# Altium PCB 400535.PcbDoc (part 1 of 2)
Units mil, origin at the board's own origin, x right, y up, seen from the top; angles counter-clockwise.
Board outline 2125.98 x 2500 mil, 4 copper layers (Top Layer, Mid-Layer 1, Mid-Layer 2, Bottom Layer), stack 93.792 mil thick; 80 components, 40 nets, 250 pads, 682 vias.
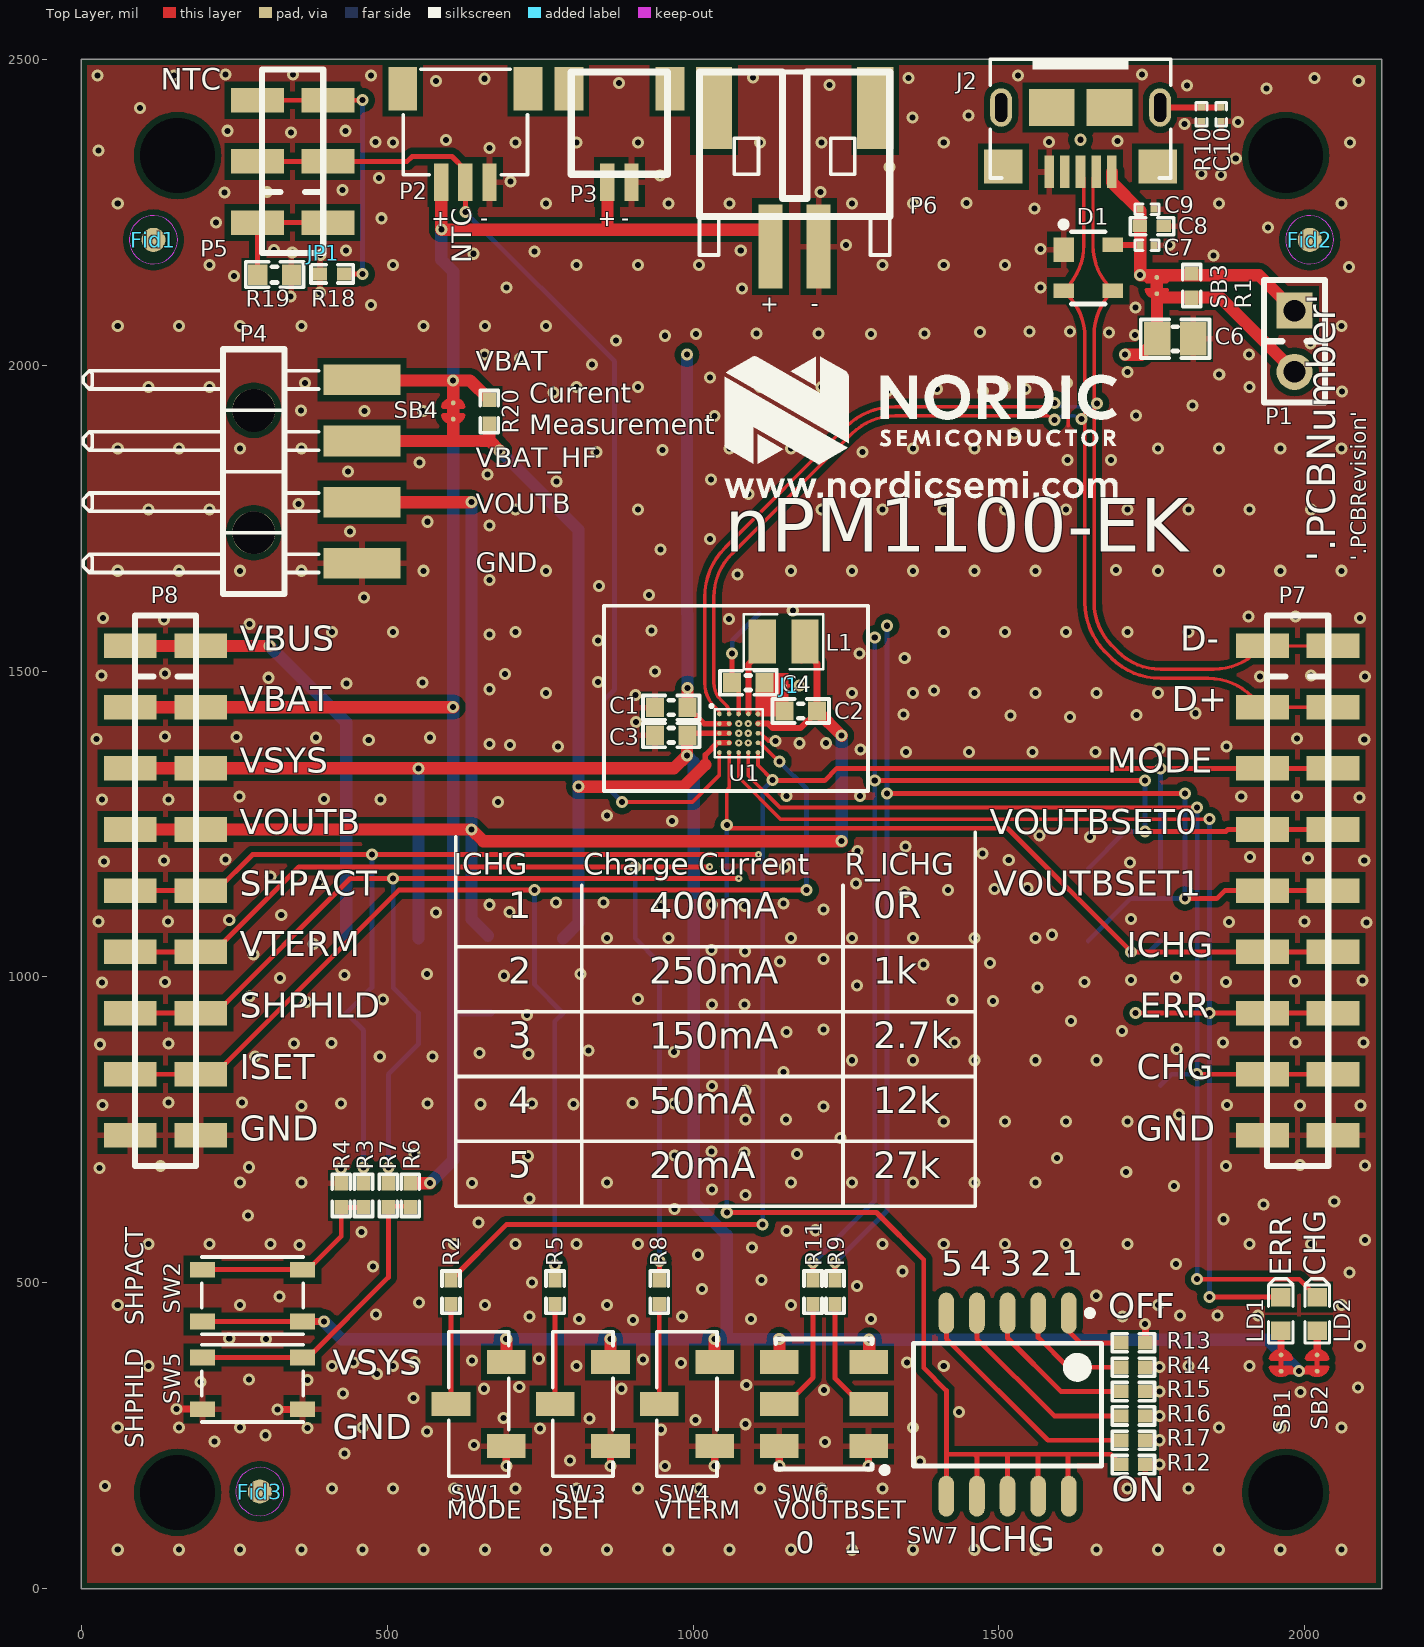
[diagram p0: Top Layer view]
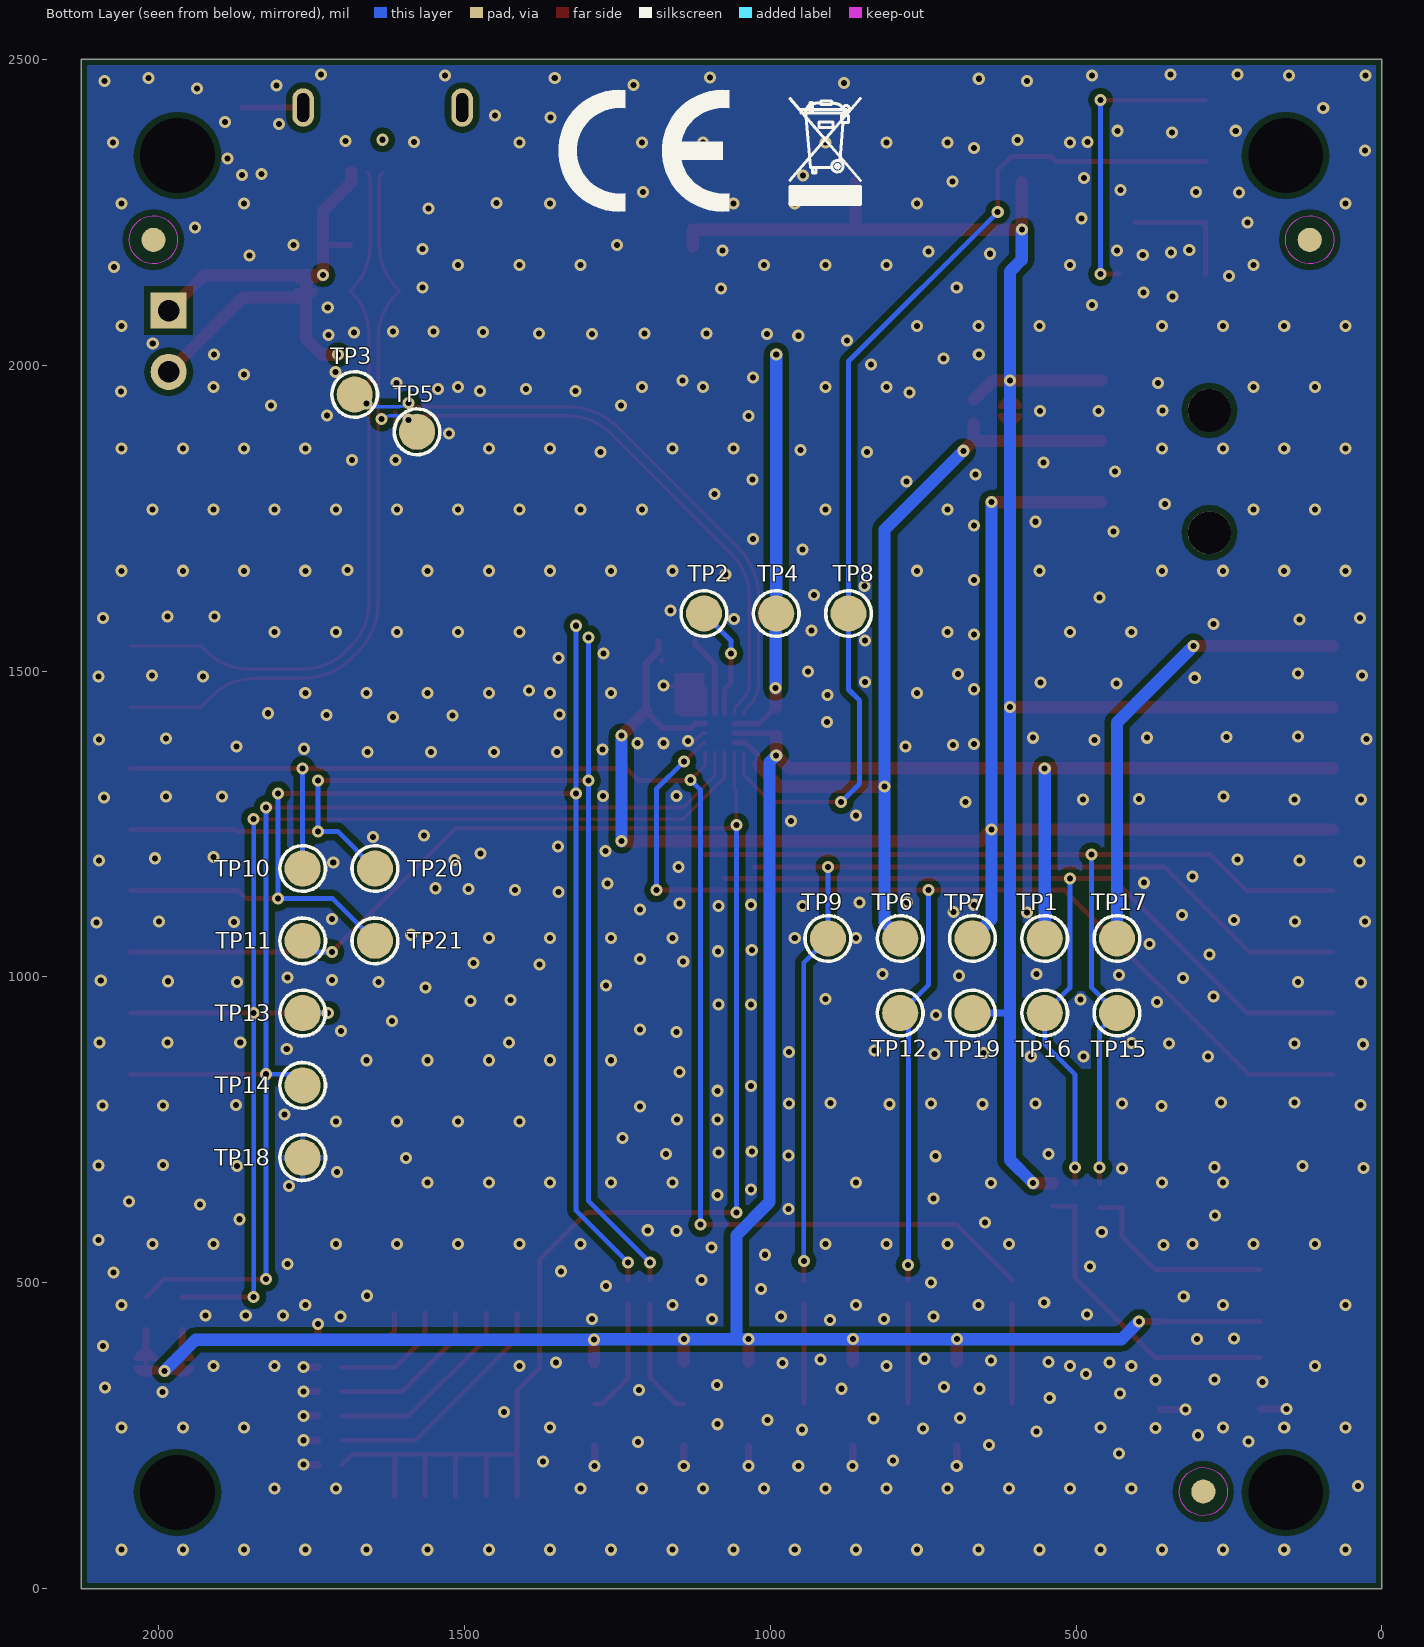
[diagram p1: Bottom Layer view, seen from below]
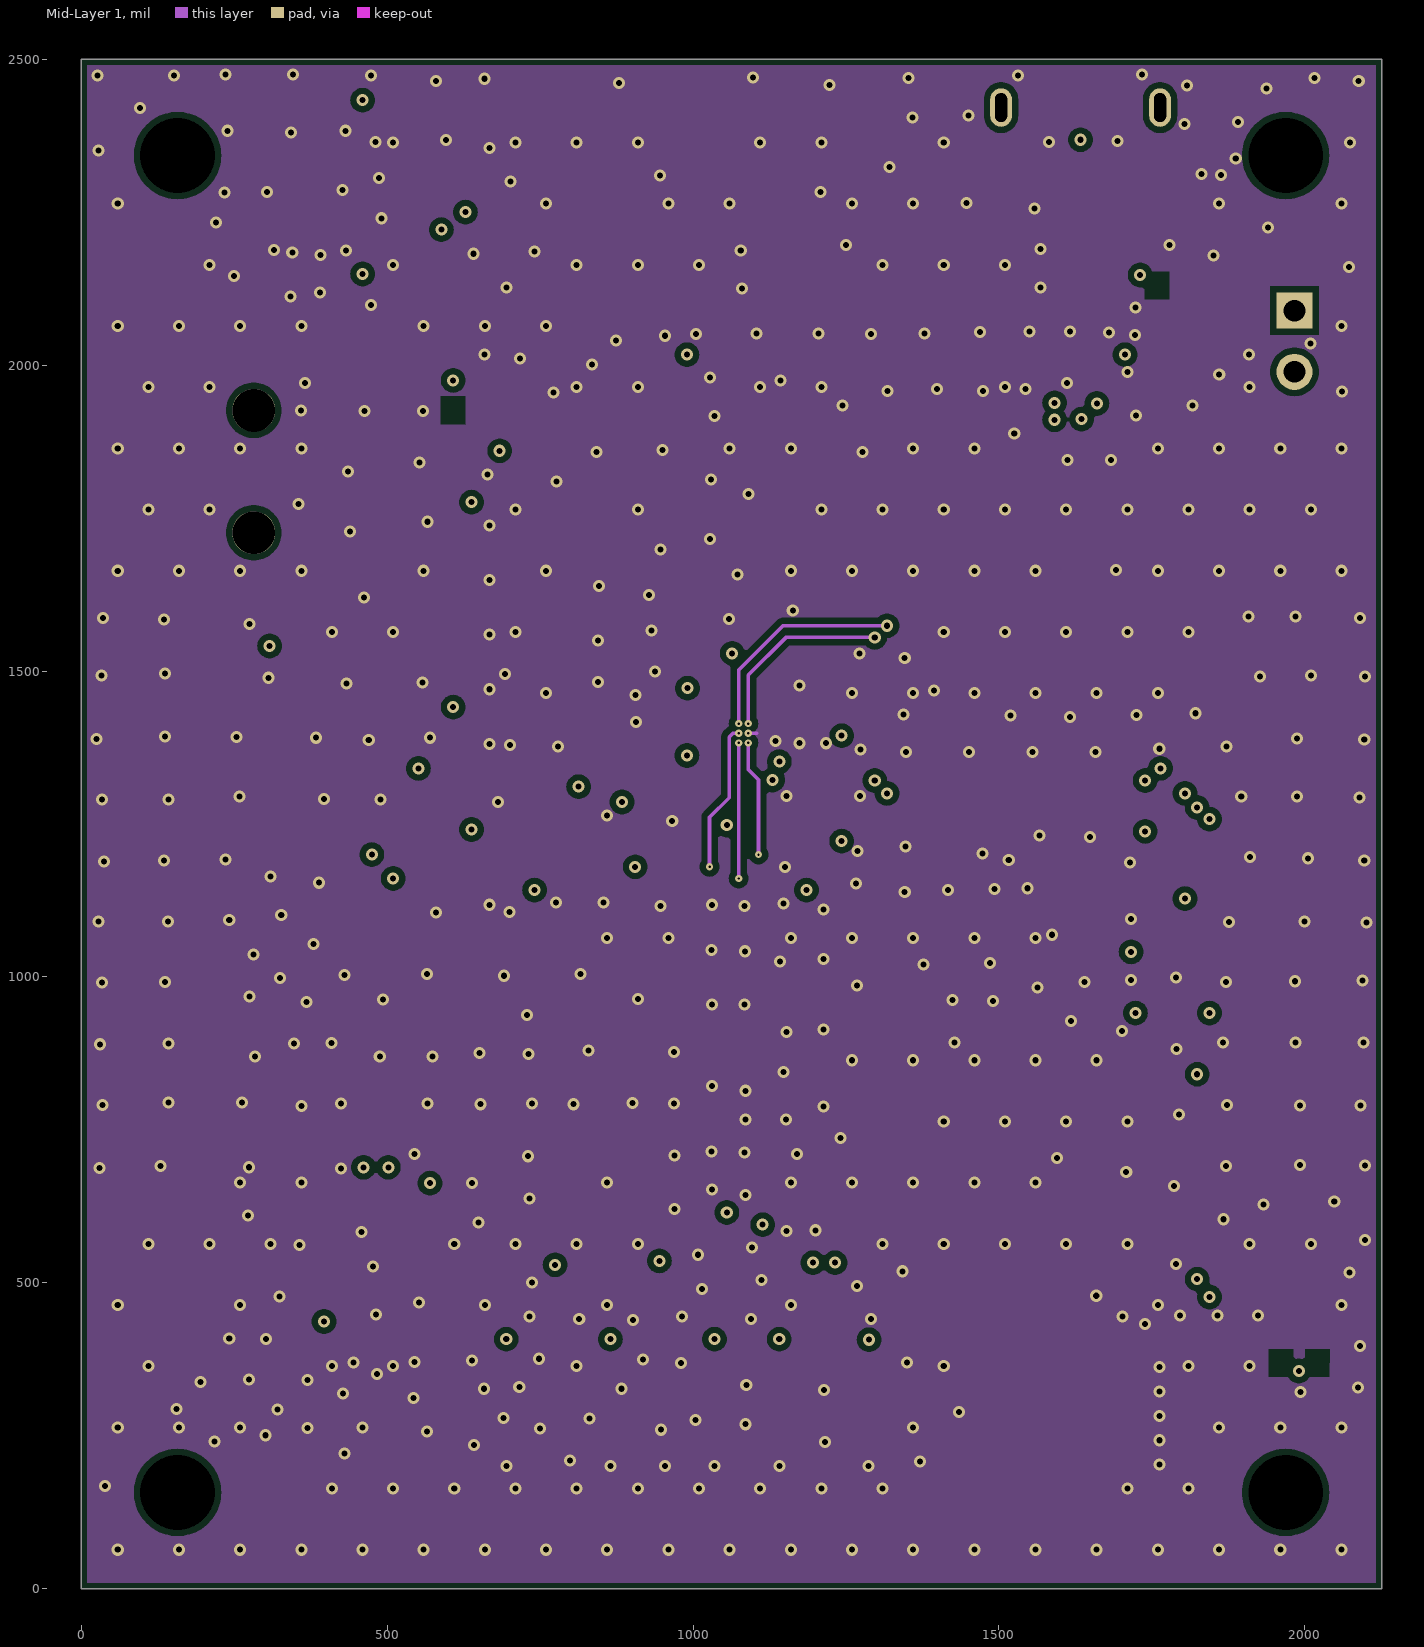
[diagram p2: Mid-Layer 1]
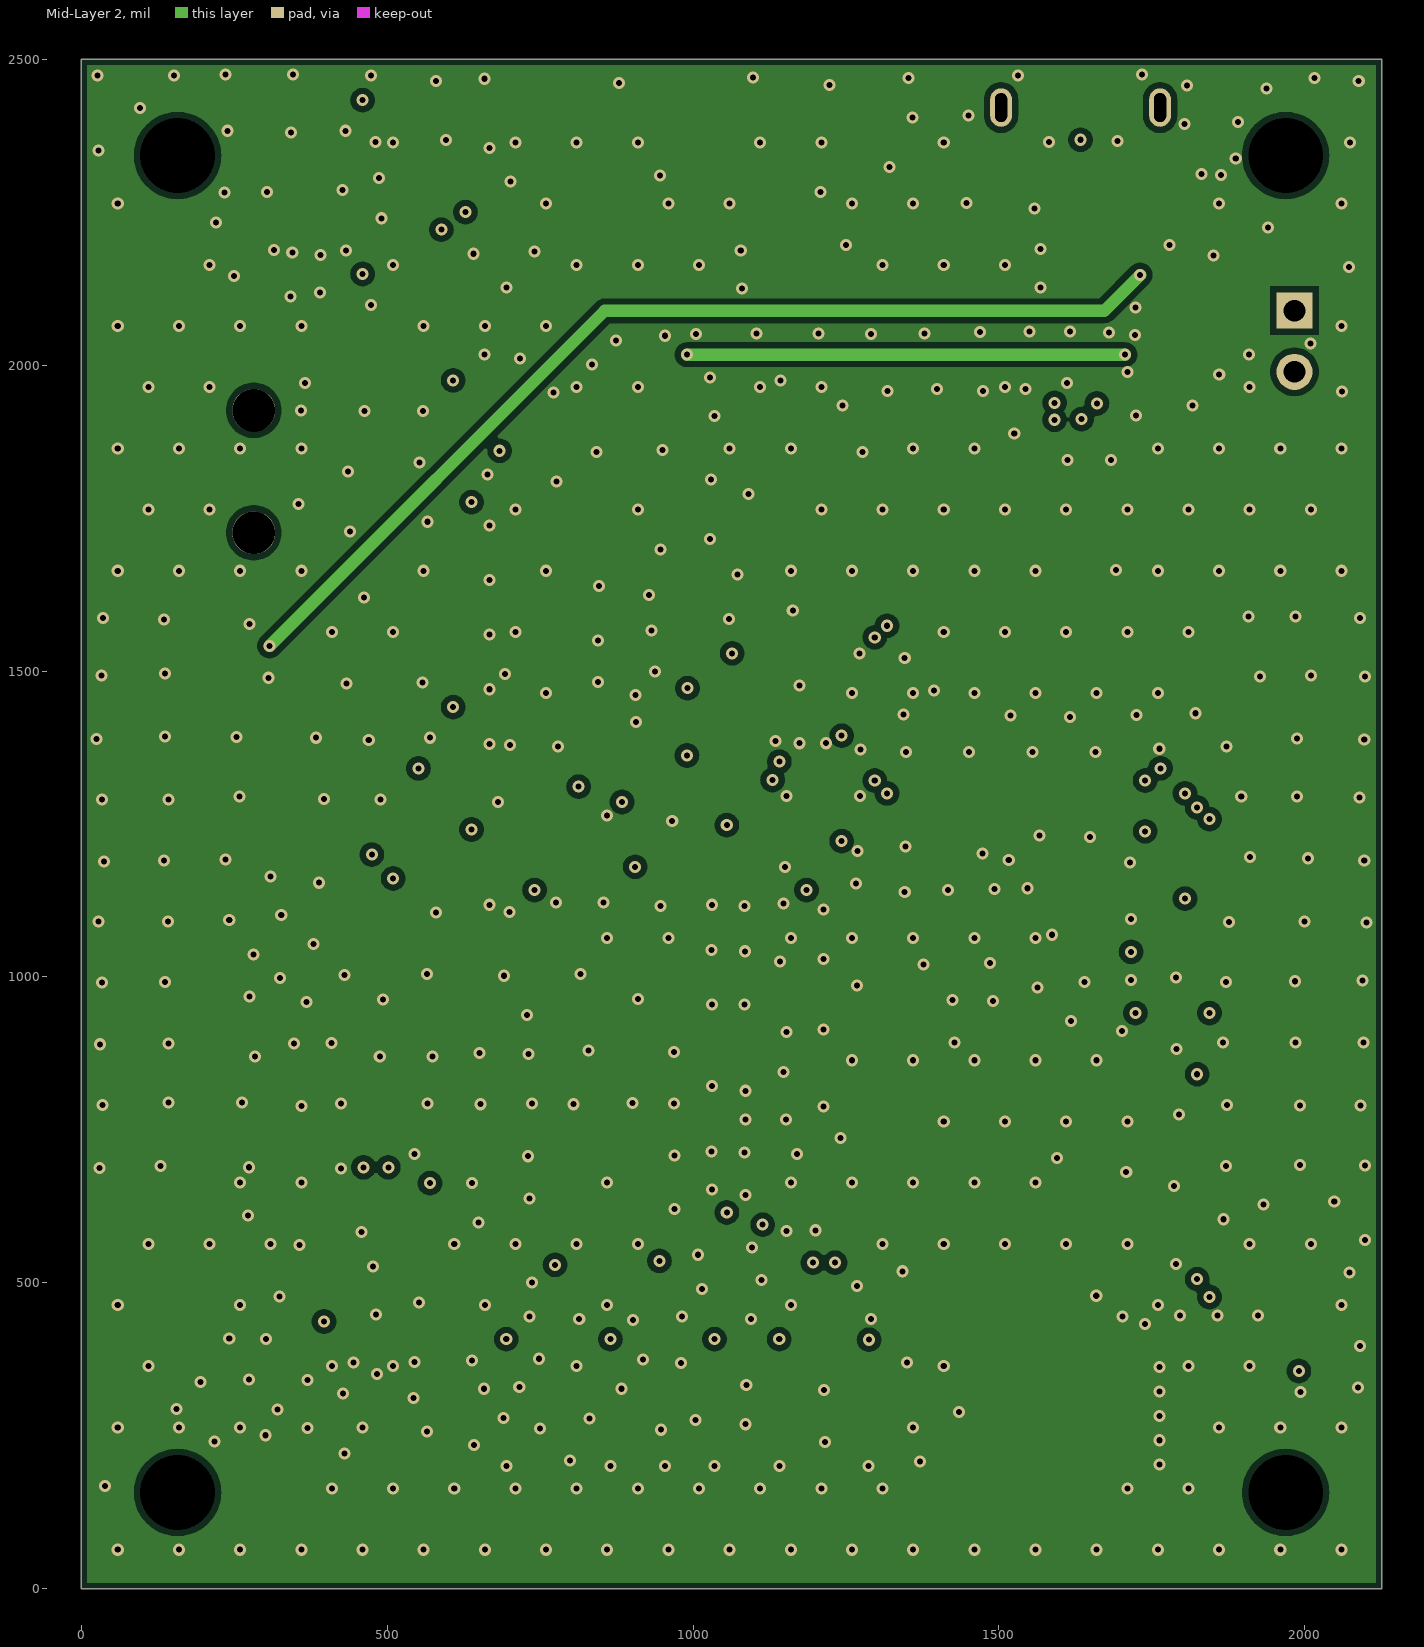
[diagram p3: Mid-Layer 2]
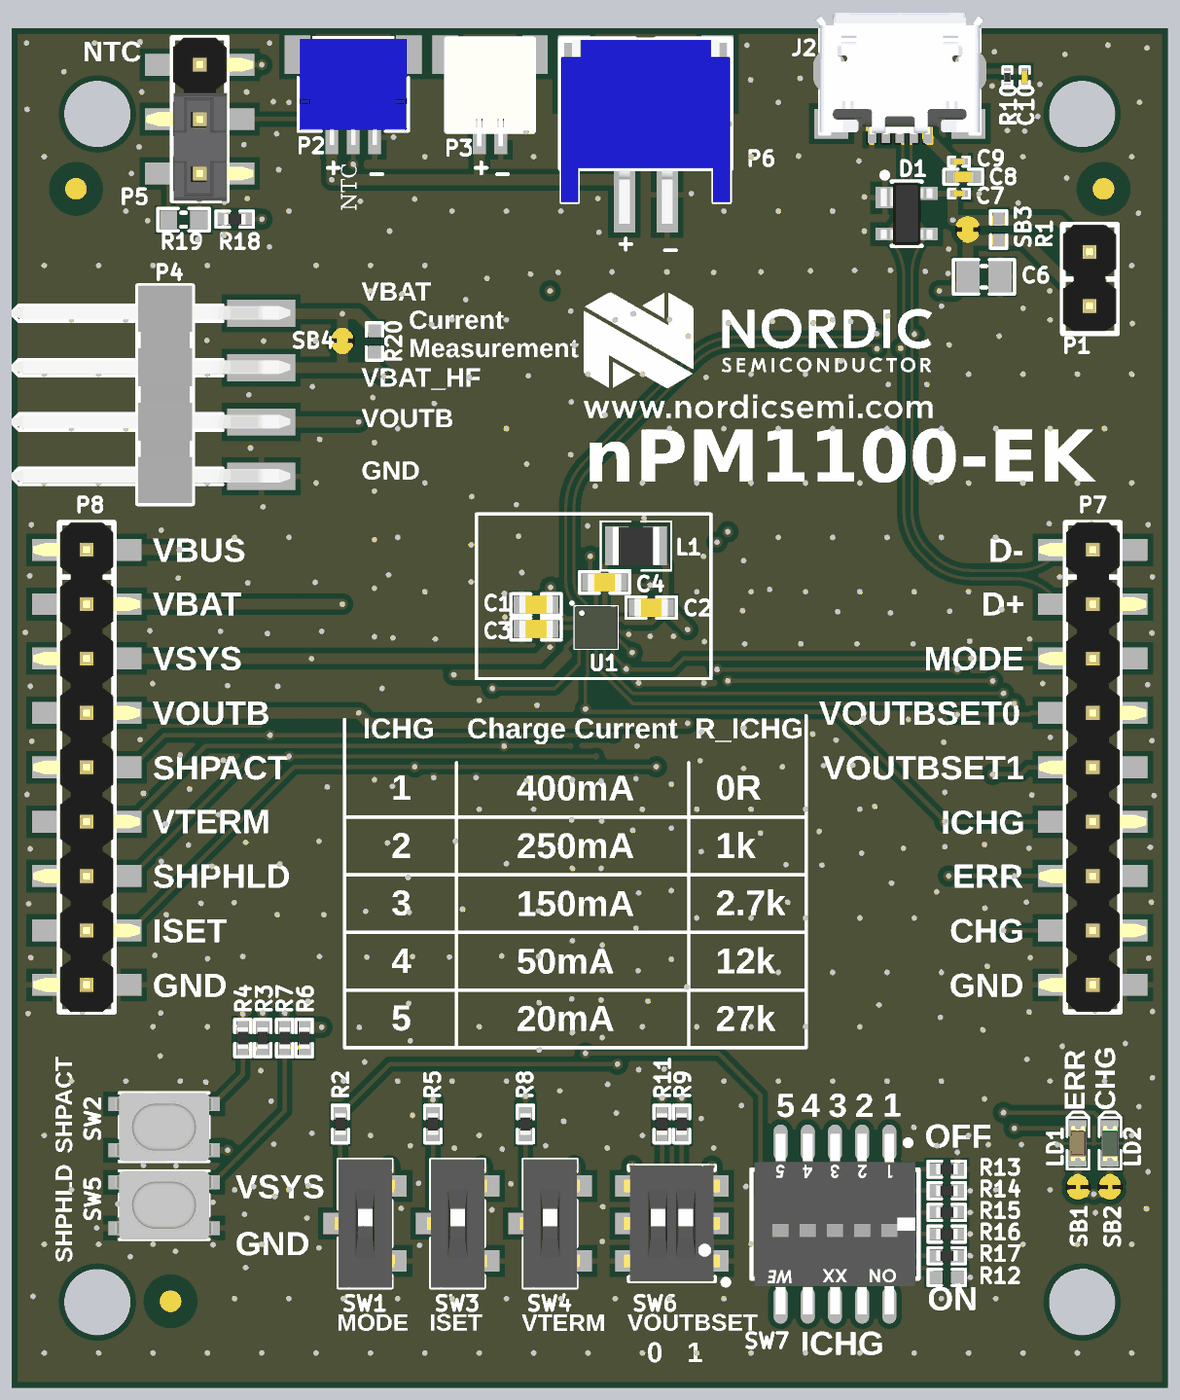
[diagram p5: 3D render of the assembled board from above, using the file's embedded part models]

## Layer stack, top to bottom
Top Solder: solder mask 0.4, Solder Resist, Dk 3.5
Top Layer: signal copper 1.4
Dielectric1: prepreg 62.9921, FR-4, Dk 4.8
Mid-Layer 1: signal copper 1.4
Dielectric2: core 12.6, FR-4, Dk 4.8
Mid-Layer 2: signal copper 1.4
Dielectric3: prepreg 12.6, FR-4, Dk 4.8
Bottom Layer: signal copper 1.4
Bottom Solder: solder mask 0.4, Solder Resist, Dk 3.5

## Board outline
0,0 2125.98,0 2125.98,2500 0,2500

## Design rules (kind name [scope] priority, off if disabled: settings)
BoardOutlineClearance [All] p1: gap=10 ignorepadtopadclearanceinfootprint=FALSE except(0: Arc-SplitContinuation Track-SplitContinuation SMDPad-SplitContinuation THPad-SplitContinuation Via-SplitContinuation Fill-SplitContinuation Poly-SplitContinuation Region-SplitContinuation Text-SplitContinuation)
Clearance Clearance_microvia [AsMM(ViaDiameter) = 0.3 vs AsMM(ViaDiameter) = 0.3] p1: gap=3.94 ignorepadtopadclearanceinfootprint=FALSE except(0: Arc-Hole Track-Hole SMDPad-Hole THPad-Hole Via-Hole Fill-Hole Poly-Hole Region-Hole Text-Hole)
Clearance ANT_Clerance [InNet('ANT')] p2: gap=5 ignorepadtopadclearanceinfootprint=FALSE except(0: Arc-Hole Track-Hole SMDPad-Hole THPad-Hole Via-Hole Fill-Hole Poly-Hole Region-Hole Text-Hole)
Clearance Polygon_Clearance [(InNamedPolygon('Top_Layer-GND')) or (InNamedPolygon('Bottom_Layer-GND')) or (InNamedPolygon('Mid_Layer_1-GND')) or (InNamedPolygon('Mid_Layer_2-GND'))] p3: gap=10 ignorepadtopadclearanceinfootprint=FALSE except(0: Arc-Hole Track-Hole SMDPad-Hole THPad-Hole Via-Hole Fill-Hole Poly-Hole Region-Hole Text-Hole)
Clearance [All] p4: gap=4.92 ignorepadtopadclearanceinfootprint=FALSE
ComponentClearance [All] p1 off: gap=10 collisioncheckmode=3 verticalgap=10 showdistances=FALSE
DiffPairsRouting [All] p1: maxlimit=10 minlimit=9.49 mostfreqgap=10 toplayer_prefgap=9.49 toplayer_minwidth=5.51 toplayer_maxwidth=15 toplayer_prefwidth=5.51 midlayer1_minwidth=5.51 midlayer1_maxwidth=15 midlayer1_prefwidth=11.06 midlayer2_mingap=10 midlayer2_minwidth=15 midlayer2_maxwidth=15 midlayer2_prefwidth=15 bottomlayer_prefgap=9.49 bottomlayer_minwidth=5.51 bottomlayer_maxwidth=15 bottomlayer_prefwidth=5.51 maxuncoupledlength=500
FabricationTestPointUsage TestPointUsage [All] p1: valid=0 allowmultiple=FALSE
FabricationTestpoint Testpoint [All] p1: side=3 testpointundercomponent=TRUE minsize=40 maxsize=100 preferedsize=60 minholesize=0 maxholesize=40 preferedholesize=32 testpointgrid=1 allowsidetop=TRUE allowsidebottom=TRUE usegrid=TRUE gridtolerance=0.01
Height [All] p1 off: minheight=0 maxheight=1000 prefheight=500
HoleSize [All] p1: absolutevalues=TRUE maxlimit=196.85 minlimit=3.94 maxpercent=80.000 minpercent=20.000
HoleToHoleClearance HoleToHoleClearance_L1L2 [InDrillLayerPair('Top Layer - Mid-Layer 1') vs InDrillLayerPair('Top Layer - Mid-Layer 1')] p1: gap=8.86 allowstackedmicrovias=TRUE
HoleToHoleClearance HoleToHoleClearance_L1L2_L1L3 [InDrillLayerPair('Top Layer - Mid-Layer 1') vs InDrillLayerPair('Top Layer - Mid-Layer 2')] p2: gap=8.86 allowstackedmicrovias=TRUE
HoleToHoleClearance HoleToHoleClearance_L1L3 [InDrillLayerPair('Top Layer - Mid-Layer 2') vs InDrillLayerPair('Top Layer - Mid-Layer 2')] p3: gap=8.86 allowstackedmicrovias=TRUE
HoleToHoleClearance HoleToHoleClearance_L1L3_L3L4 [InDrillLayerPair('Top Layer - Mid-Layer 2') vs InDrillLayerPair('Mid-Layer 2 - Mid-Layer 3')] p4: gap=8.86 allowstackedmicrovias=TRUE
HoleToHoleClearance HoleToHoleClearance_L3L4 [InDrillLayerPair('Mid-Layer 2 - Mid-Layer 3') vs InDrillLayerPair('Mid-Layer 2 - Mid-Layer 3')] p5: gap=8.86 allowstackedmicrovias=TRUE
HoleToHoleClearance HoleToHoleClearance_L3L4_L4L6 [InDrillLayerPair('Mid-Layer 2 - Mid-Layer 3') vs InDrillLayerPair('Mid-Layer 3 - Bottom Layer')] p6: gap=8.86 allowstackedmicrovias=TRUE
HoleToHoleClearance HoleToHoleClearance_L4L6 [InDrillLayerPair('Mid-Layer 3 - Bottom Layer') vs InDrillLayerPair('Mid-Layer 3 - Bottom Layer')] p7: gap=8.86 allowstackedmicrovias=TRUE
HoleToHoleClearance HoleToHoleClearance_L1L2_L1L6 [InDrillLayerPair('Top Layer - Mid-Layer 1') vs InDrillLayerPair('Top Layer - Bottom Layer')] p8: gap=10.83 allowstackedmicrovias=FALSE
HoleToHoleClearance HoleToHoleClearance_L1L3_L1L6 [InDrillLayerPair('Top Layer - Mid-Layer 2') vs InDrillLayerPair('Top Layer - Bottom Layer')] p9: gap=10.83 allowstackedmicrovias=FALSE
HoleToHoleClearance HoleToHoleClearance_L3L4_L1L6 [InDrillLayerPair('Mid-Layer 2 - Mid-Layer 3') vs InDrillLayerPair('Top Layer - Bottom Layer')] p10: gap=10.83 allowstackedmicrovias=FALSE
HoleToHoleClearance HoleToHoleClearance_L4L6_L1L6 [InDrillLayerPair('Mid-Layer 3 - Bottom Layer') vs InDrillLayerPair('Top Layer - Bottom Layer')] p11: gap=10.83 allowstackedmicrovias=FALSE
HoleToHoleClearance HoleToHoleClearance_L1L6 [InDrillLayerPair('Top Layer - Bottom Layer') vs InDrillLayerPair('Top Layer - Bottom Layer')] p12: gap=17.72 allowstackedmicrovias=FALSE
MinimumAnnularRing [All] p1 off: minimumring=6
PolygonConnect PolygonConnect_1 [isVia and innet(gnd)] p1: connectstyle=Direct reliefconductorwidth=10 reliefentries=4 polygonreliefangle="90 Angle" airgapwidth=10
PolygonConnect [All] p2: connectstyle=Relief reliefconductorwidth=10 reliefentries=4 polygonreliefangle="90 Angle" airgapwidth=10
RoutingVias [All] p1: holewidth=12 width=24 viastyle="Through Hole" minholewidth=3.94 minwidth=11.81 maxholewidth=28 maxwidth=50 useviatemplates=TRUE viatemplateguid#1={93AF73D0-991B-4F91-A86F-AF45B5E71B0E} viatemplateguid#2={23E904B5-25B2-4AFA-AFBF-BB17C8E28516} viatemplatename#1=v30h10m0 viatemplatename#2=v50h25m0mx0
SilkToSolderMaskClearance SilkscreenOverComponentPads [IsPad] p1: minsilkscreentomaskgap=10 clearancetoexposedcopper=TRUE
SolderMaskExpansion [IsVia] p1: expansion=3 istentingtop=TRUE
Width [All] p1: maxlimit=20 minlimit=5.91 preferedwidth=12 minimp=50.000000 maximp=50.000000 favimp=50.000000
22 further rules are at their usual default settings.

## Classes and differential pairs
component class pca10123_sheet1_cover: Fid1 Fid2 Fid3
component class pca10123-sheet2_nPM1100: C1 C2 C3 C4 J1 L1 TP1 TP2 TP3 TP4 TP5 TP6 TP7 TP8 TP9 TP10 TP11 TP12 TP13 TP14 TP15 TP16 TP18 TP20 TP21 U1
differential pair class USB2: D
component class pca10123-sheet3_misc: C6 C7 C8 C9 C10 D1 J2 JP1 LD1 LD2 P1 P2 P3 P4 P5 P6 P7 P8 R1 R2 R3 R4 R5 R6 R7 R8 R9 R10 R11 R12 R13 R14 R15 R16 R17 R18 R19 R20 SB1 SB2 SB3 SB4 SW1 SW2 SW3 SW4 SW5 SW6 SW7 TP17 TP19
differential pair D: +D_P -D_N

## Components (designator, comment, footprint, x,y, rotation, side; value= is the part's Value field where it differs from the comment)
C1 "2.2µF" CAPC1608X06L 964.39,1440.3 r0 top
C2 "10µF" CAPC1608X06L 1176,1434.72 r0 top
C3 "10µF" CAPC1608X06L 964.39,1395.02 r0 top
C4 "10µF" CAPC1608X06L 1090.37,1480.98 r180 top
C6 "DNM" CAPC2012X11L_NC 1788,2043 r180 top
C7 "100nF" CAPC0603X03L_C 1742,2196 r0 top
C8 "4.7µF" CAPC1005X04L 1750,2227 r0 top
C9 "10nF" CAPC0603X03L_C 1742,2255 r0 top
C10 "4.7nF" CAPC0603X03L_C 1863,2410 r270 top
D1 "PRTR5V0U2X" SOT190P230X110-4L 1646,2159 r0 top
Fid1 "Fiducial mark" Fiducial 118.11,2204.72 r90 top value=N.A.
Fid2 "Fiducial mark" Fiducial 2007.87,2204.72 r90 top value=N.A.
Fid3 "Fiducial mark" Fiducial 292,159 r90 top value=N.A.
J1 "N.A." "2 PIN STARPOINT" 1158.28,1476.06 r180 top net-tie
J2 "MicroUSB-B" USB-Micro-B-RA-SMD-PiP 1633.35,2315.65 r270 top locked
JP1 "Shunt 2.54mm" Shunt_2.54mm 395.68,2182.93 r90 top
L1 "2.2µH" INDC2016X10N 1148,1548 r0 top
LD1 "L0603G" LED_0603_R 1960.87,449.31 r270 top
LD2 "L0603G" LED_0603_G 2019.92,449.31 r270 top
P1 "Pin List 1x2" LIST_1x2 1983,2039 r270 top
P2 "HDR-3, 1mm" SM03B-SRSS-TB 628,2299.02 r180 top
P3 "HDR-2, 1mm" SM02B-SRSS-TB 879.74,2299.02 r180 top
P4 "Pin List 1x4, Angled" LIST_ANG_1x4-SMD-2.54MM 459.01,1826 r270 top
P5 "Pin List 1x3" LIST_1x3_SMD 345.68,2232.93 r90 top
P6 "HDR-2, 2mm" S2B-PH-SM4-TB 1166,2193.7 r180 top
P7 "Pin List 1x9" LIST_1x9_SMD 1988.19,1541 r270 top locked
P8 "Pin List 1x9" LIST_1x9_SMD 137.8,1541 r270 top
R1 "DNM" RESC1005X04L_NC 1815,2130.02 r90 top
R2 "10k" RESC1005X04L 604.45,485 r90 top
R3 "10k" RESC1005X04L 461.42,643 r90 top
R4 "10k" RESC1005X04L 425,643 r90 top
R5 "10k" RESC1005X04L 774.59,485 r90 top
R6 "10k" RESC1005X04L 538,643 r90 top
R7 "10k" RESC1005X04L 501.96,643 r90 top
R8 "10k" RESC1005X04L 944.72,485 r90 top
R9 "4k7" RESC1005X04L 1232,485 r90 top
R10 "1M0" RESC0603X03L_C 1831,2410 r270 top
R11 "4k7" RESC1005X04L 1196,485 r90 top
R12 "DNM" RESC1005X04L_NC 1719.68,203 r180 top
R13 "0R" RESC1005X04L 1719.68,402 r180 top
R14 "1k" RESC1005X04L 1719.68,362.2 r180 top
R15 "2k7" RESC1005X04L 1719.68,322.4 r180 top
R16 "12k" RESC1005X04L 1719.68,282.6 r180 top
R17 "27k" RESC1005X04L 1719.68,242.8 r180 top
R18 "10k" RESC1005X04L 410,2149 r0 top
R19 "DNM" RESC1608X06L_NC 316,2148 r180 top
R20 "DNM" RESC1005X04L_NC 667,1924 r90 top
SB1 "Solderbridge" Solderbridge_Shorted 1961,369 r90 top net-tie
SB2 "Solderbridge" Solderbridge_Shorted 2020,369 r90 top net-tie
SB3 "Solderbridge" Solderbridge_Shorted_Power 1758,2130.02 r270 top net-tie
SB4 "Solderbridge" Solderbridge_Shorted_Power 608,1925 r90 top net-tie
SW1 "Switch" CJS-120xA 649.72,302.01 r90 top
SW2 "PB SW" C&K_PTS810 280.01,479.25 r0 top
SW3 "Switch" CJS-120xA 819.86,302.01 r90 top
SW4 "Switch" CJS-120xA 990,302.01 r90 top
SW5 "PB SW" C&K_PTS810 280.01,335.72 r0 top
SW6 "Switch" CAS-D20A 1214,302.01 r90 top
SW7 "DIP-SW-5" SOIC127P840X265-10N 1514,301 r270 top
TP1 "Ø1.5mm,SMD" TP_SMD_D1.5mm 551.18,1062.99 r180 bottom
TP2 "Ø1.5mm,SMD" TP_SMD_D1.5mm 1108.11,1594 r180 bottom
TP3 "Ø1.5mm,SMD" TP_SMD_D1.5mm 1679,1952 r180 bottom
TP4 "Ø1.5mm,SMD" TP_SMD_D1.5mm 990,1594 r90 bottom
TP5 "Ø1.5mm,SMD" TP_SMD_D1.5mm 1577,1891 r180 bottom
TP6 "Ø1.5mm,SMD" TP_SMD_D1.5mm 787.4,1062.99 r270 bottom
TP7 "Ø1.5mm,SMD" TP_SMD_D1.5mm 669.29,1062.99 r270 bottom
TP8 "Ø1.5mm,SMD" TP_SMD_D1.5mm 871.89,1594 r270 bottom
TP9 "Ø1.5mm,SMD" TP_SMD_D1.5mm 905.51,1062.99 r270 bottom
TP10 "Ø1.5mm,SMD" TP_SMD_D1.5mm 1764,1177.17 r270 bottom
TP11 "Ø1.5mm,SMD" TP_SMD_D1.5mm 1764,1059.06 r270 bottom
TP12 "Ø1.5mm,SMD" TP_SMD_D1.5mm 787.4,941 r270 bottom
TP13 "Ø1.5mm,SMD" TP_SMD_D1.5mm 1764,940.95 r270 bottom
TP14 "Ø1.5mm,SMD" TP_SMD_D1.5mm 1764,822.84 r270 bottom
TP15 "Ø1.5mm,SMD" TP_SMD_D1.5mm 433.07,941 r270 bottom
TP16 "Ø1.5mm,SMD" TP_SMD_D1.5mm 551.18,941 r270 bottom
TP17 "Ø1.5mm,SMD" TP_SMD_D1.5mm 433.07,1062.99 r180 bottom
TP18 "Ø1.5mm,SMD" TP_SMD_D1.5mm 1764,704.73 r270 bottom
TP19 "Ø1.5mm,SMD" TP_SMD_D1.5mm 669.29,941 r180 bottom
TP20 "Ø1.5mm,SMD" TP_SMD_D1.5mm 1645.89,1177.17 r180 bottom
TP21 "Ø1.5mm,SMD" TP_SMD_D1.5mm 1645.89,1059.06 r180 bottom
U1 "nPM1100-CAAAC0" BGA25C40P5X5_200X200X50 1074.62,1398.31 r0 top locked

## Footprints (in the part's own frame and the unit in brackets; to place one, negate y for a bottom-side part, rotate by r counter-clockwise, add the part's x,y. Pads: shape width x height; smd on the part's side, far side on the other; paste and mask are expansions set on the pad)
"2 PIN STARPOINT" [mil]
  round 5.98 smd paste-196.85 mask-196.85: 1(8,0) 2(-8,0)
  Top Layer region: -11,-3 11,-3 11,3 -11,3
BGA25C40P5X5_200X200X50 [mm] "BGA, 25-Leads, Body 2.00x2.00mmx0.50mm, Pitch 0.40mm"
  round 0.193 smd mask+0.075: A1(-0.8,0.8) A2(-0.4,0.8) A3(0,0.8) A4(0.4,0.8) A5(0.8,0.8) B1(-0.8,0.4) B2(-0.4,0.4) B3(0,0.4) B4(0.4,0.4) B5(0.8,0.4) C1(-0.8,0) C2(-0.4,0) C3(0,0) C4(0.4,0) C5(0.8,0) D1(-0.8,-0.4) D2(-0.4,-0.4) D3(0,-0.4) D4(0.4,-0.4) D5(0.8,-0.4) E1(-0.8,-0.8) E2(-0.4,-0.8) E3(0,-0.8) E4(0.4,-0.8) E5(0.8,-0.8)
  silkscreen extent -1.18,-1 1,1.18, body extent -1,-1 1,1, height 0.5
C&K_PTS810 [mm] "Microminiature SMT Top Actuated"
  rect 1.05x0.65 smd: 1(-2.075,1.075) 1(2.075,1.075) 2(-2.075,-1.075) 2(2.075,-1.075)
  silkscreen extent -2.1,-1.6 2.1,1.6, body extent -2.29,-1.6 2.29,1.6, height 2.5
CAPC0603X03L_C [mm] "Chip Capacitor, 2-Leads, Body 0.6x0.3mm, IPC High Density"
  rect 0.27x0.3 smd mask+0.05: 1(-0.285,0) 2(0.285,0)
  silkscreen extent -0.49,-0.22 0.49,0.22, body extent -0.3,-0.15 0.31,0.15, height 0.3
CAPC1005X04L [mm] "Chip Capacitor, 2-Leads, Body 1.0x0.5mm, IPC High Density"
  rect 0.6x0.5 smd: 1(-0.5,0) 2(0.5,0)
  silkscreen extent -0.9,-0.35 0.9,0.35, body extent -0.51,-0.25 0.51,0.25, height 0.5
CAPC1608X06L [mm] "Chip Capacitor, 2-Leads, Body 1.6x0.8mm, IPC High Density"
  rect 0.75x0.8 smd: 1(-0.675,0) 2(0.675,0)
  silkscreen extent -1.17,-0.5 1.17,0.5, body extent -0.8,-0.43 0.8,0.43, height 0.8
CAPC2012X11L_NC [mm] "Chip Capacitor, 2-Leads, Body 2.0x1.3mm, IPC High Density"
  rect 1.1x1.4 smd: 1(-0.75,0) 2(0.75,0)
  silkscreen extent -1.43,-0.8 1.42,0.8
CAS-D20A [mm] "SLIDE SWITCH 2xSPDT J HOOK"
  rect 1x1.6 smd: 1(-1.75,-1.85) 2(0,-1.85) 3(1.75,-1.85) 4(-1.75,1.85) 5(0,1.85) 6(1.75,1.85)
  silkscreen extent -2.84,-2.62 2.7,2, body extent -2.7,-2.27 2.7,2.28, height 2.5
CJS-120xA [mm] "Slide Switches - SPDT, SMD, ON-ON"
  rect 1x1.6 smd: 1(1.75,-1.15) 2(0,1.15) 3(-1.75,-1.15)
  silkscreen extent -3,-1.25 3,1.25, body extent -3,-1.4 3,1.45, height 2.5
Fiducial [mm] "Fiducial Mark"
  round 1 smd paste-0.508: 0(0,0)
  round 1 smd far side paste-0.508: 0(0,0)
  Top Layer keep-out circle w0.01: c0,0 r1
  Bottom Layer keep-out circle w0.01: c0,0 r1
INDC2016X10N [mm] "Chip Inductor, 2-Leads, Body 2.00x1.60mm, IPC Medium Density"
  rect 1.13x1.82 smd: 1(-0.885,0) 2(0.885,0)
  silkscreen extent -1.65,-1.14 1.65,1.14, body extent -1.1,-0.9 1.1,0.9, height 1
LED_0603_G [mil] "SMD Super Bright LED, GREEN"
  rect 30x32 smd: 1(-27.5,0) 2(27.5,0)
  silkscreen extent -58,-20 48,20, body extent -32,-16 32,16, height 24
LED_0603_R [mil] "SMD Super Bright LED, RED"
  rect 30x32 smd: 1(-27.5,0) 2(27.5,0)
  silkscreen extent -58,-20 48,20, body extent -32,-16 32,16, height 24
LIST_1x2 [mm] "Pin List, 2.54mm through hole"
  rect 1.5x1.5 hole 0.9: 1(-1.27,0)
  round 1.5 hole 0.9: 2(1.27,0)
  silkscreen extent -2.54,-1.27 2.54,1.27, body extent -2.54,-1.27 2.44,1.23, height 8.2
LIST_1x3_SMD [mm] "Pin List, 2.54mm, SMD"
  rect 1.02x2.19 smd: 1(0,1.465) 1(0,-1.465) 2(2.54,-1.465) 2(2.54,1.465) 3(5.08,-1.465) 3(5.08,1.465)
  silkscreen extent -1.27,-1.27 6.35,1.27, body extent -1.27,-2.5 6.35,2.5, height 9.82
LIST_1x9_SMD [mm] "Pin List, 2.54mm, SMD"
  rect 1.02x2.19 smd: 1(0,1.465) 1(0,-1.465) 2(2.54,1.465) 2(2.54,-1.465) 3(5.08,-1.465) 3(5.08,1.465) 4(7.62,-1.465) 4(7.62,1.465) 5(10.16,-1.465) 5(10.16,1.465) 6(12.7,-1.465) 6(12.7,1.465) 7(15.24,-1.465) 7(15.24,1.465) 8(17.78,-1.465) 8(17.78,1.465) 9(20.32,-1.465) 9(20.32,1.465)
  silkscreen extent -1.27,-1.27 21.59,1.27, body extent -1.27,-2.5 21.59,2.5, height 9.82
LIST_ANG_1x4-SMD-2.54MM [mm] "Pin List, 2.54mm, Surface Mount, Angled"
  round 1.78 hole 1.78 unplated: 0(-2.54,-4.496) 0(2.54,-4.496)
  rect 1.27x3.18 smd: 1(-3.81,0) 2(-1.27,0) 3(1.27,0) 4(3.81,0)
  silkscreen extent -5.08,-11.58 5.08,-1.8, body extent -5.1,-11.61 5.06,1.35, height 3.03
RESC0603X03L_C [mm] "Chip Resistor, 2-Leads, Body 0.6x0.3mm, IPC High Density"
  rect 0.27x0.3 smd: 1(-0.285,0) 2(0.285,0)
  silkscreen extent -0.49,-0.22 0.49,0.22, body extent -0.3,-0.15 0.3,0.15, height 0.23
RESC1005X04L [mm] "Chip Resistor, 2-Leads, Body 1.0x0.5mm, IPC High Density"
  rect 0.6x0.55 smd mask+0.05: 1(-0.5,0) 2(0.5,0)
  silkscreen extent -0.87,-0.38 0.88,0.38, body extent -0.5,-0.25 0.5,0.25, height 0.3
RESC1005X04L_NC [mm] "Chip Resistor, 2-Leads, Body 1.0x0.5mm, IPC High Density"
  rect 0.6x0.55 smd mask+0.05: 1(-0.5,0) 2(0.5,0)
  silkscreen extent -0.87,-0.38 0.88,0.38
RESC1608X06L_NC [mm] "Chip Resistor, 2-Leads, Body 1.6x0.8mm, IPC High Density"
  rect 0.8x0.85 smd: 1(-0.7,0) 2(0.7,0)
  silkscreen extent -1.2,-0.53 1.2,0.53
S2B-PH-SM4-TB [mm] "JST, PH connector, side entry SMD, 2mm pitch"
  rect 1.5x3.4 smd: 0(-3.35,-5.75) 0(3.35,-5.75)
  rect 1x3.5 smd: 1(-1,0) 2(1,0)
  silkscreen extent -3.95,-7.25 3.95,0.35, body extent -3.95,-7.25 3.95,1.35, height 5.5
Shunt_2.54mm [mil]
  body extent 0,0 198,98, height 300
SM02B-SRSS-TB [mm] "JST, SH connector, side entry SMD, 1mm pitch"
  rect 1.2x1.8 smd: 0(-2.1,-3.875) 0(2.1,-3.875)
  rect 0.6x1.55 smd: 1(-0.5,0) 2(0.5,0)
  silkscreen extent -2,-4.57 2,-0.33, body extent -1.99,-4.58 1.99,0.41, height 3
SM03B-SRSS-TB [mm] "JST, SH connector, side entry SMD, 1mm pitch"
  rect 1.2x1.8 smd: 0(-2.6,-3.875) 0(2.6,-3.875)
  rect 0.6x1.55 smd: 1(-1,0) 2(0,0) 3(1,0)
  silkscreen extent -2.57,-4.68 2.58,-0.3, body extent -2.5,-4.61 2.5,0.34, height 2.95
SOIC127P840X265-10N [mm] "SOIC, 10-Leads, Body 7.52x5.80mm, Pitch 1.27mm, IPC Medium Density"
  oval 1.7x0.65 smd: 1(-3.8,2.54) 2(-3.8,1.27) 3(-3.8,0) 4(-3.8,-1.27) 5(-3.8,-2.54) 6(3.8,-2.54) 7(3.8,-1.27) 8(3.8,0) 9(3.8,1.27) 10(3.8,2.54)
  silkscreen extent -3.92,-3.9 2.55,3.9, body extent -4.22,-3.76 4.22,3.76, height 2.6
Solderbridge_Shorted [mm]
  round 0.2 smd paste-10: 1(-0.338,0) 2(0.338,0)
  Top Layer region: -0.102,-0.432 -0.178,-0.505 -0.296,-0.467 -0.361,-0.424 -0.434,-0.351 -0.488,-0.292 -0.546,-0.193 -0.574,-0.099 -0.569,0.122 -0.544,0.193 -0.46,0.33 -0.376,0.411 -0.284,0.469 -0.183,0.5 -0.132,0.483 -0.102,0.43
  Top Layer region: 0.102,0.432 0.178,0.505 0.296,0.467 0.361,0.424 0.434,0.351 0.488,0.292 0.546,0.193 0.574,0.099 0.569,-0.122 0.544,-0.193 0.46,-0.33 0.376,-0.411 0.284,-0.469 0.183,-0.5 0.132,-0.483 0.102,-0.43
  Top Layer lines w0.152: -0.178,0.431 ccw(c-0.068,0) -0.178,-0.431 ; 0.178,0.431 cw(c0.068,0) 0.178,-0.431
  Top Layer lines w0.203: -0.338,0 0.338,0
Solderbridge_Shorted_Power [mm]
  round 0.2 smd paste-10: 1(-0.338,0) 2(0.338,0)
  Top Layer region: -0.102,-0.432 -0.178,-0.505 -0.296,-0.467 -0.361,-0.424 -0.434,-0.351 -0.488,-0.292 -0.546,-0.193 -0.574,-0.099 -0.569,0.122 -0.544,0.193 -0.46,0.33 -0.376,0.411 -0.284,0.469 -0.183,0.5 -0.132,0.483 -0.102,0.43
  Top Layer region: 0.102,0.432 0.178,0.505 0.296,0.467 0.361,0.424 0.434,0.351 0.488,0.292 0.546,0.193 0.574,0.099 0.569,-0.122 0.544,-0.193 0.46,-0.33 0.376,-0.411 0.284,-0.469 0.183,-0.5 0.132,-0.483 0.102,-0.43
  Top Layer lines w0.152: 0.178,-0.431 ccw(c0.068,0) 0.178,0.431 ; -0.178,-0.431 cw(c-0.068,0) -0.178,0.431
  Top Layer lines w0.508: 0.338,0 -0.338,0
SOT190P230X110-4L [mm] "SOT143, 4-Leads, Body 3.0x2.5mm (max), Pitch 1.90mm, IPC High Density"
  rect 0.85x1 smd: 1(-1.025,0.75)
  rect 0.85x0.6 smd: 2(-1.025,-0.95) 3(1.025,-0.95) 4(1.025,0.95)
  silkscreen extent -1.15,-1.5 0.7,1.92, body extent -1.21,-1.46 1.21,1.46, height 1
TP_SMD_D1.5mm [mm] "Test point - pad 1.5mm"
  round 1.5 smd paste-5: 1(0,0)
  silkscreen extent -0.95,-0.95 0.95,0.95, body extent -0.75,-0.75 0.75,0.75, height 0.05
USB-Micro-B-RA-SMD-PiP [mm] "Micro USB B SMT"
  rect 1.35x0.4 smd mask+0.075: 1(0,1.3) 2(0,0.65) 3(0,0) 4(0,-0.65) 5(0,-1.3)
  oval 1.6x0.9 hole 0.5 slot 1.2 at 0 deg: 6(-2.675,3.3) 6(-2.675,-3.3)
  oval 2x1.5 on Top Paste: 6(-2.675,3.3) 6(-2.675,-3.3)
  rect 1.55x1.9 smd: 6(-2.675,1.2) 6(-2.675,-1.2)
  rect 1.4x1.6 smd: 6(-0.225,3.2) 6(-0.225,-3.2)
  silkscreen extent -4.75,-3.75 0.25,3.75, body extent -5.43,-3.93 0.28,3.93, height 2.84

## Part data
C1: library part C0603-2µ2-25V-X5R, "Capacitor, Ceramic, X5R, ±10%, 25V", Manufacturer=Murata, Manufacturer Part Number=GRM188R61E225KA12D, Part number IPS=N.A., Supplier Part Number 1=490-10731-1-ND
C2 C3 C4: library part 0603-10u-10V-X7T-GRM188, "CAP CER 10UF 10V X7T 0603", Manufacturer=Murata, Manufacturer Part Number=GRM188D71A106MA73, Part number IPS=00000004696, Part number Norautron=N.A., Supplier Part Number 1=490-7200-1-ND
C6: library part C0805-N.C., "Not mounted", Manufacturer=N.A.
C7: library part C0201-100n, "Capacitor, X5R, ±10%", Manufacturer=N.A., Part number IPS="00000001248, 00000002505"
C8: library part C0402-4µ7, "Capacitor, X5R, ±20%", Manufacturer=N.A., Part number IPS="00000001251, 00000007165", Supplier Part Number 1=490-13252-1-ND
C9: library part C0201-10n, "Capacitor, X7R, ±10%", Manufacturer=N.A., Part number IPS=00000003480
C10: library part C0201-4n7, "Chip Cap 0201 4.7nF 10% 10V X7R", Manufacturer=N.A., Part number IPS=00000001243
D1: "Ultra low capacitance double rail-to-rail ESD protection diode", Manufacturer="NXP Semiconductors", Part number IPS=00000009951, Part number Norautron=N.A., Supplier Part Number 1=568-4140-1-ND
Fid1 Fid2 Fid3: library part Fid-Mark, "Fiducial Mark", Manufacturer=N.A.
J1: library part "2 pin starpoint", "Starpoint"
J2: library part USB-Micro-B-RA-SMD-PiP, "MicroUSB-B-SMT", Manufacturer="Allen Creations Corp.", Manufacturer Part Number=AJU55-BS2111-L, Part number IPS=00000007790, Part number Norautron=N.A.
JP1: library part "SHUNT JUMPER 2.54mm BLACK GOLD", "SHUNT JUMPER .1\" BLACK GOLD", Manufacturer=3M, Manufacturer Part Number=969102-0000-DA, Part number IPS=N.A., Supplier Part Number 1=3M9580-ND
L1: library part CIGT201610EH2R2MNE, "FIXED IND 2.2UH 2.5A 87MOHM SMD", Manufacturer="Samsung Electro-Mechanics", Part number IPS=N.A., Supplier Part Number 1=1276-6901-1-ND
LD1: library part ASMT-RR45-AQ902, "LED, Red, 0603, Vf=2V, - 40 to +100°C", Manufacturer=Avago, Part number IPS=N.A., Supplier Part Number 1=516-2005-1-ND
LD2: library part ASMT-RF45-AN002, "LED, Yellow Green, 0603, Vf=2V, - 40 to +100°C", Manufacturer=Avago, Part number IPS=N.A., Supplier Part Number 1=516-2522-1-ND
P1: "Pin List 1x2, 2.54mm (100mil)", Manufacturer=N.A.
P2: library part SM03B-SRSS-TB, "1.0mm pitch connector side entry SMD", Manufacturer="JST Sales America Inc.", Manufacturer Part Number=SM03B-SRSS-TB(LF)(SN), Part number IPS=00000001785, Part number Norautron=N.A.
P3: library part SM02B-SRSS-TB, "1.0mm pitch connector side entry SMD", Manufacturer="JST Sales America Inc.", Manufacturer Part Number=SM02B-SRSS-TB(LF)(SN), Part number IPS=00000007791, Part number Norautron=N.A.
P4: library part "Pin List Ang 1x4 SMD, 2.54mm", "Pin List 1x4, 2.54mm (100mil), Right Angled, SMD", Manufacturer=W-CON, Manufacturer Part Number=1125B-1104S0Z135CR02, Part number IPS=00000004780, Part number Norautron=N.A.
P5: library part "Pin List 1x3 SMD", "Pin List 1x3, 2.54mm (100mil), SMD", Manufacturer=W-CON, Manufacturer Part Number=1125-1103S3M116CR02, Part number IPS=N.A.
P6: library part S2B-PH-SM4-TB, "2.0mm pitch connector side entry SMD", Manufacturer="JST Sales America Inc.", Manufacturer Part Number=S2B-PH-SM4-TB(LF)(SN), Part number IPS=N.A.
P7 P8: library part "Pin List 1x9 SMD", "Pin List 1x9, 2.54mm (100mil), SMD", Manufacturer=W-CON, Manufacturer Part Number=1125-1109S0M116R2, Part number IPS=N.A.
R1 R12 R20: library part R0402-N.C., "Not mounted", Manufacturer=N.A.
R2 R3 R4 R5 R6 R7 R8 R18: library part R0402-10k, "Resistor, ±1%, 0.063W", Manufacturer=N.A., Part number IPS=00000002093, Supplier Part Number 1=173-8864
R9 R11: library part R0402-4K7, "Resistor, ±1%, 0.063W", Manufacturer=N.A., Part Number=R0402-4k7, Part number IPS=00000003433, Supplier Part Number 1=173-8858
R10: library part R0201-1M0, "Resistor, ±1%, 0.05W", Manufacturer=N.A., Part number IPS=00000001418
R13: library part R0402-0R, "Resistor, ±5%, 0.063W", Manufacturer=N.A., Part number IPS=00000007128, Supplier Part Number 1=146-9661
R14: library part R0402-1k0, "Resistor, ±1%, 0.063W", Manufacturer=N.A., Part number IPS=00000002218, Supplier Part Number 1=173-8850
R15: library part R0402-2k7, "Resistor, ±1%, 0.063W", Manufacturer=N.A., Supplier Part Number 1=173-8855
R16: library part R0402-12k, "Resistor, ±1%, 0.063W", Manufacturer=N.A., Supplier Part Number 1=173-8865
R17: library part R0402-27k, "Resistor, ±1%, 0.063W", Manufacturer=N.A., Part number IPS=00000004188, Supplier Part Number 1=173-8869
R19: library part R0603-N.C., "Not mounted", Manufacturer=N.A.
SB1 SB2: library part "Solderbridge Shorted", "Shorted Solderbridge", Manufacturer=N.A.
SB3 SB4: library part "Solderbridge Shorted Power", "Shorted Solderbridge Power", Manufacturer=N.A.
SW1 SW3 SW4: library part CJS-1200TA, "SMD slide Switch (ON-ON)", Manufacturer="Copal Electronics Inc", Part number IPS=00000009982, Part number Norautron=N.A., Supplier Part Number 1=563-1021-2-ND
SW2 SW5: library part "PTS810 SJK 250 SMTR LFS", "Tactile Switch, SPNO, SMD, 260gf, 4.2x3.2x2.5mm", Manufacturer=C&K, Part number IPS=00000001259, Part number Norautron=N.A., Supplier Part Number 1=CKN10503TR-ND
SW6: library part CAS-D20TA, "SMD slide Switch 2xSPDT", Manufacturer="Copal Electronics Inc", Part number IPS=N.A., Supplier Part Number 1=CASD20JTR-ND
SW7: library part DIP-SW5-SPST, "SWITCH SLIDE DIP SPST 25MA 24V", Manufacturer="Wurth Elektronik", Manufacturer Part Number=416131160805, Part number IPS=N.A., Supplier Part Number 1=732-3855-1-ND
TP1 TP2 TP3 TP4 TP5 TP6 TP7 TP8 TP9 TP10 TP11 TP12 TP13 TP14 TP15 TP16 TP17 TP18 TP19 TP20 TP21: library part TP_SMD_Ø1.5MM, "1.5mm circular SMD testpad", Manufacturer="Nordic Semiconductor", Manufacturer Part Number=N.A.
U1: "Li-Ion/Li-Polymer USB battery charger with a high efficiency buck regulator", Manufacturer="Nordic Semiconductor", Part number IPS=N.A.

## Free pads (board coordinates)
  round 5 hole 122.05 unplated: 0(157.48,157.48) 0(157.48,2342.52) 0(1968.5,2342.52) 0(1968.5,157.48)
  round 11.81 on Mech16 mask+3: 2(1058.62,1027.56) 3(1074.37,1027.56) 4(1074.37,1043.31) 5(1058.62,1043.31) 6(1058.62,1059.06) 7(1074.37,1059.06) 8(1145,1105)

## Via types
v1: diameter 19.68, hole 9.84, Top Layer to Bottom Layer, tented both sides, 673 vias
v2: diameter 11.81, hole 3.94, Top Layer to Mid-Layer 1, tented top, 8 vias
v3: diameter 11.81, hole 3.94, Top Layer to Mid-Layer 1, tented both sides, 1 vias

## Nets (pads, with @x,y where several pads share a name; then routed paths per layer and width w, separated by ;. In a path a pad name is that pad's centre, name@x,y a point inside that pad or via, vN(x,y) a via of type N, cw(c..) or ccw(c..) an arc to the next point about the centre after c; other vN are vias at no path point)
CHG: LD2.1 P7.8 TP14.1 U1.E4 | length 2061.6
  Top Layer w5.91: U1.E4@1090.37,1366.81 1090.37,1328.63 1142,1277 v1(1824,1277)
  Top Layer w8: v1(1824,506) 1990.74,506 LD2.1@2019.92,476.81 ; v1(1824,841) P7.8@1930.51,841 P7.8@2045.87,841
  Bottom Layer w8: TP14.1@1764,822.84 1782.16,841 v1(1824,841) ; v1(1824,506) v1(1824,841) ; v1(1824,1277) v1(1824,841)
D_N: D1.3 J2.2 P7.1 TP3.1 U1.A1 | length 2176
  Top Layer w5.51: U1.A1@1043.13,1429.8 ccw(c1033.81,1429.8) 1040.4,1436.39 1035.39,1441.39 cw(c1074.97,1480.97) 1019,1480.97 1019,1620.58 cw(c1134,1620.58) 1052.68,1701.9 1249.1,1898.32 cw(c1330.42,1817) 1330.42,1932 1578.12,1932 ccw(c1578.12,1950.21) v1@1591,1937.33 ; J2.2@1658.94,2315.65 ccw(c1671.73,2302.87) 1653.65,2302.87 1653.65,2195.73 ccw(c1753.65,2195.73) 1682.94,2125.02 D1.3@1686.35,2121.6 1684.79,2120.03 ccw(c1755.5,2049.32) 1655.5,2049.32 1655.5,1611.92 ccw(c1755.5,1611.92) 1684.79,1541.21 1694,1532 ccw(c1764.01,1602.01) 1764.01,1503 1851.09,1503 ccw(c1851.09,1603) 1921.8,1532.29 P7.1@1930.51,1541 P7.1@2045.87,1541
  Bottom Layer w5.51: v1(1591,1938.33) ccw(c1606.29,1953.63) 1606.29,1932 1647.12,1932 ccw(c1647.12,1950.21) v1(1660,1937.33)
D_P: D1.2 J2.3 P7.2 TP5.1 U1.A2 | length 2157.3
  Top Layer w5.51: U1.A2@1058.87,1429.8 cw(c1060.68,1431.61) 1058.13,1431.61 1058.13,1435.21 ccw(c1046.87,1435.21) 1054.83,1443.17 1046,1452 cw(c1074.97,1480.97) 1034,1480.97 1034,1620.58 cw(c1134,1620.58) 1063.29,1691.29 1259.71,1887.71 cw(c1330.42,1817) 1330.42,1917 1578.12,1917 cw(c1578.12,1898.79) v1@1591,1911.67 ; J2.3@1633.35,2315.65 cw(c1620.57,2302.87) 1638.65,2302.87 1638.65,2196.02 cw(c1538.65,2196.02) 1609.36,2125.31 D1.2@1605.65,2121.6 1611.21,2116.03 cw(c1540.5,2045.32) 1640.5,2045.32 1640.5,1611.92 ccw(c1755.5,1611.92) 1674.18,1530.6 1683.39,1521.39 ccw(c1764.01,1602.01) 1764.01,1488 1842.09,1488 cw(c1842.09,1388) 1912.8,1458.71 P7.2@1930.51,1441 P7.2@2045.87,1441
  Bottom Layer w5.51: v1(1591,1910.67) cw(c1606.29,1895.37) 1606.29,1917 1622.12,1917 cw(c1622.12,1898.79) v1(1635,1911.67)
DEC: C4.2 TP2.1 U1.A3 | length 187
  Top Layer w7.87: v1(1064,1529) 1063.79,1528.8 C4.2@1063.79,1480.98 1074.62,1470.16 U1.A3@1074.62,1429.8
  Bottom Layer w7.87: v1(1064,1529) 1064,1549.89 TP2.1@1108.11,1594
